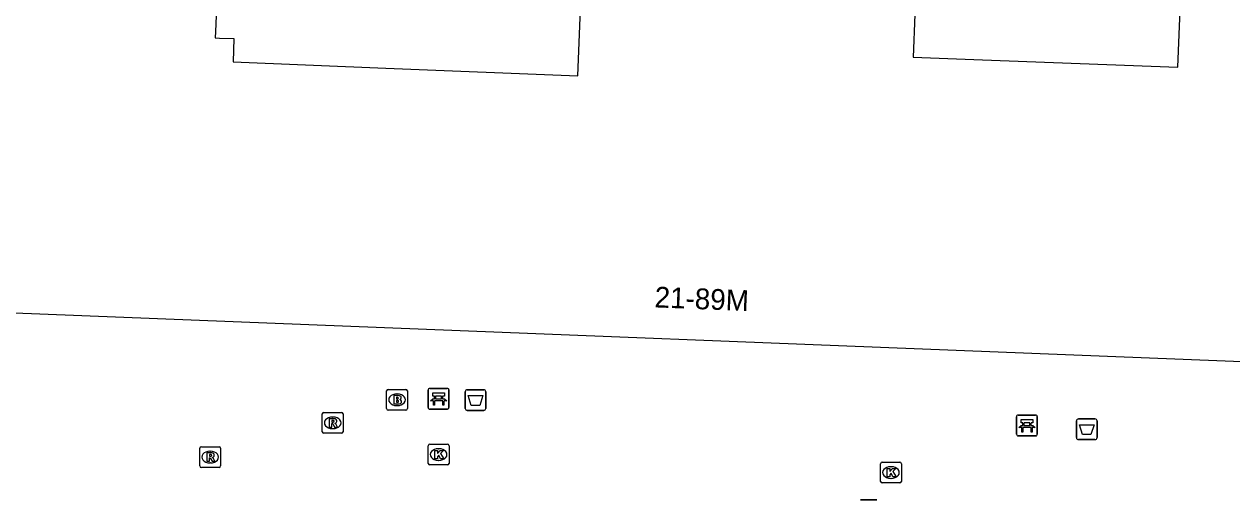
# Model space of a CAD drawing. Extents: x 160891 to 161384, y 386490 to 386907.
# Drawn here: x 161211.9 to 161270, y 386833.9 to 386856.8 of the extents above; entities that cross this region are included whole.
import ezdxf

# ---------------------------------------------------------------- set-up
doc = ezdxf.new("R2010")
doc.units = 0
for name, color, linetype in [('IMGEO_Afvalbak', 7, 'Continuous'), ('IMGEO_Bank', 7, 'Continuous'), ('IMGEO_Brandkraan', 7, 'Continuous'), ('IMGEO_Kolk', 7, 'Continuous'), ('IMGEO_Pand', 7, 'Continuous'), ('IMGEO_Pand_nummerreeks', 7, 'Continuous'), ('IMGEO_Reclamebord', 7, 'Continuous'), ('IMGEO_Rioolput', 7, 'Continuous')]:
    doc.layers.add(name, color=color, linetype=linetype)

msp = doc.modelspace()

# ---------------------------------------------------------------- linework, layer by layer
at = {"layer": 'IMGEO_Afvalbak'}
for p, q in [((161233.09, 386838.273), (161233.09, 386839.073)), ((161233.09, 386839.073), (161233.09, 386838.273)), ((161233.19, 386839.173), (161233.98, 386839.173)), ((161233.98, 386839.173), (161233.19, 386839.173)), ((161234.08, 386839.073), (161234.08, 386838.273)), ((161234.08, 386838.273), (161234.08, 386839.073)), ((161233.98, 386838.173), (161233.19, 386838.173)), ((161233.19, 386838.173), (161233.98, 386838.173)), ((161262.495, 386836.869), (161262.495, 386837.669)), ((161262.495, 386837.669), (161262.495, 386836.869)), ((161262.595, 386837.769), (161263.385, 386837.769)), ((161263.385, 386837.769), (161262.595, 386837.769)), ((161263.485, 386837.669), (161263.485, 386836.869)), ((161263.485, 386836.869), (161263.485, 386837.669)), ((161263.385, 386836.769), (161262.595, 386836.769)), ((161262.595, 386836.769), (161263.385, 386836.769))]:
    msp.add_line(p, q, dxfattribs=at)
for points in [[(161233.233, 386838.887), (161233.937, 386838.887), (161233.788, 386838.417), (161233.382, 386838.417), (161233.233, 386838.887)], [(161262.638, 386837.483), (161263.342, 386837.483), (161263.193, 386837.013), (161262.787, 386837.013), (161262.638, 386837.483)]]:
    msp.add_lwpolyline(points, dxfattribs=at)
for centre, start, end in [((161233.19, 386839.073), 90, 180), ((161233.19, 386839.073), 90, 180), ((161233.98, 386839.073), 0, 90), ((161233.98, 386839.073), 360, 90), ((161233.19, 386838.273), 180, 270), ((161233.19, 386838.273), 180, 270), ((161233.98, 386838.273), 270, 0), ((161233.98, 386838.273), 270, 0), ((161262.595, 386837.669), 90, 180), ((161262.595, 386837.669), 90, 180), ((161263.385, 386837.669), 0, 90), ((161263.385, 386837.669), 360, 90), ((161262.595, 386836.869), 180, 270), ((161262.595, 386836.869), 180, 270), ((161263.385, 386836.869), 270, 0), ((161263.385, 386836.869), 270, 0)]:
    msp.add_arc(centre, 0.1, start, end, dxfattribs=at)
at = {"layer": 'IMGEO_Bank'}
for p, q in [((161231.308, 386838.312), (161231.308, 386839.153)), ((161231.308, 386839.153), (161231.308, 386838.312)), ((161231.383, 386839.237), (161232.224, 386839.237)), ((161232.224, 386839.237), (161231.383, 386839.237)), ((161231.617, 386838.743), (161231.617, 386838.849)), ((161231.661, 386838.849), (161231.661, 386838.743)), ((161231.949, 386838.855), (161231.667, 386838.855)), ((161231.955, 386838.743), (161231.955, 386838.849)), ((161231.999, 386838.849), (161231.999, 386838.743)), ((161232.308, 386839.162), (161232.308, 386838.321)), ((161232.308, 386838.321), (161232.308, 386839.162)), ((161232.233, 386838.237), (161231.392, 386838.237)), ((161231.392, 386838.237), (161232.233, 386838.237)), ((161232.005, 386838.635), (161231.612, 386838.635)), ((161231.667, 386838.737), (161231.949, 386838.737)), ((161259.612, 386837.027), (161259.612, 386837.868)), ((161259.612, 386837.868), (161259.612, 386837.027)), ((161259.687, 386837.952), (161260.528, 386837.952)), ((161260.528, 386837.952), (161259.687, 386837.952)), ((161260.612, 386837.877), (161260.612, 386837.036)), ((161260.612, 386837.036), (161260.612, 386837.877)), ((161260.309, 386837.35), (161259.916, 386837.35)), ((161259.921, 386837.458), (161259.921, 386837.564)), ((161259.965, 386837.564), (161259.965, 386837.458)), ((161260.253, 386837.57), (161259.971, 386837.57)), ((161259.971, 386837.452), (161260.253, 386837.452)), ((161260.259, 386837.458), (161260.259, 386837.564)), ((161260.303, 386837.564), (161260.303, 386837.458)), ((161260.537, 386836.952), (161259.696, 386836.952)), ((161259.696, 386836.952), (161260.537, 386836.952))]:
    msp.add_line(p, q, dxfattribs=at)
for points in [[(161231.611, 386838.855), (161231.525, 386838.855), (161231.525, 386839.016), (161232.088, 386839.016), (161232.088, 386838.855), (161232.005, 386838.855)], [(161231.555, 386838.635), (161231.413, 386838.635), (161231.525, 386838.737), (161231.611, 386838.737)], [(161231.605, 386838.628), (161231.605, 386838.421), (161231.562, 386838.421), (161231.562, 386838.628)], [(161232.005, 386838.737), (161232.088, 386838.737), (161232.2, 386838.635), (161232.061, 386838.635)], [(161232.055, 386838.628), (161232.055, 386838.421), (161232.011, 386838.421), (161232.011, 386838.628)], [(161259.915, 386837.57), (161259.829, 386837.57), (161259.829, 386837.731), (161260.392, 386837.731), (161260.392, 386837.57), (161260.309, 386837.57)], [(161259.859, 386837.35), (161259.717, 386837.35), (161259.829, 386837.452), (161259.915, 386837.452)], [(161259.909, 386837.343), (161259.909, 386837.136), (161259.866, 386837.136), (161259.866, 386837.343)], [(161260.309, 386837.452), (161260.392, 386837.452), (161260.504, 386837.35), (161260.365, 386837.35)], [(161260.359, 386837.343), (161260.359, 386837.136), (161260.315, 386837.136), (161260.315, 386837.343)]]:
    msp.add_lwpolyline(points, dxfattribs=at)
for centre, radius, start, end in [((161231.386, 386839.159), 0.0779, 92.4484, 184.28452), ((161231.386, 386839.159), 0.0779, 92.4484, 184.28452), ((161231.61, 386838.848), 0.00671, 2.89567, 87.10433), ((161231.667, 386838.848), 0.00671, 92.89567, 177.10433), ((161231.949, 386838.848), 0.00671, 2.89567, 87.10433), ((161232.006, 386838.848), 0.00671, 92.89567, 177.10433), ((161232.23, 386839.159), 0.0779, 2.4484, 94.28452), ((161232.23, 386839.159), 0.0779, 2.4484, 94.28452), ((161231.386, 386838.315), 0.0779, 182.4484, 274.28452), ((161231.386, 386838.315), 0.0779, 182.4484, 274.28452), ((161231.555, 386838.628), 0.00671, 2.89567, 87.10433), ((161231.612, 386838.628), 0.00671, 92.89567, 177.10433), ((161231.61, 386838.744), 0.00671, 272.89567, 357.10433), ((161231.667, 386838.744), 0.00671, 182.89567, 267.10433), ((161231.949, 386838.744), 0.00671, 272.89567, 357.10433), ((161232.006, 386838.744), 0.00671, 182.89567, 267.10433), ((161232.004, 386838.628), 0.00671, 2.89567, 87.10433), ((161232.061, 386838.628), 0.00671, 92.89567, 177.10433), ((161232.23, 386838.315), 0.0779, 272.4484, 4.28452), ((161232.23, 386838.315), 0.0779, 272.4484, 4.28452), ((161259.69, 386837.874), 0.0779, 92.4484, 184.28452), ((161259.69, 386837.874), 0.0779, 92.4484, 184.28452), ((161260.534, 386837.874), 0.0779, 2.4484, 94.28452), ((161260.534, 386837.874), 0.0779, 2.4484, 94.28452), ((161259.859, 386837.343), 0.00671, 2.89567, 87.10433), ((161259.916, 386837.343), 0.00671, 92.89567, 177.10433), ((161259.914, 386837.563), 0.00671, 2.89567, 87.10433), ((161259.914, 386837.459), 0.00671, 272.89567, 357.10433), ((161259.971, 386837.563), 0.00671, 92.89567, 177.10433), ((161259.971, 386837.459), 0.00671, 182.89567, 267.10433), ((161260.253, 386837.563), 0.00671, 2.89567, 87.10433), ((161260.253, 386837.459), 0.00671, 272.89567, 357.10433), ((161260.31, 386837.563), 0.00671, 92.89567, 177.10433), ((161260.31, 386837.459), 0.00671, 182.89567, 267.10433), ((161260.308, 386837.343), 0.00671, 2.89567, 87.10433), ((161260.365, 386837.343), 0.00671, 92.89567, 177.10433), ((161259.69, 386837.03), 0.0779, 182.4484, 274.28452), ((161259.69, 386837.03), 0.0779, 182.4484, 274.28452), ((161260.534, 386837.03), 0.0779, 272.4484, 4.28452), ((161260.534, 386837.03), 0.0779, 272.4484, 4.28452)]:
    msp.add_arc(centre, radius, start, end, dxfattribs=at)
at = {"layer": 'IMGEO_Brandkraan'}
for p, q in [((161229.31, 386838.262), (161229.31, 386839.114)), ((161229.385, 386839.188), (161230.237, 386839.188)), ((161229.798, 386838.968), (161229.823, 386838.968)), ((161230.311, 386839.114), (161230.311, 386838.262)), ((161229.821, 386838.408), (161229.796, 386838.408)), ((161230.237, 386838.188), (161229.385, 386838.188))]:
    msp.add_line(p, q, dxfattribs=at)
for points in [[(161229.31, 386838.262), (161229.31, 386839.114)], [(161229.385, 386839.188), (161230.237, 386839.188)], [(161229.658, 386838.888), (161229.658, 386838.488), (161229.871, 386838.488)], [(161229.889, 386838.888), (161229.658, 386838.888)], [(161229.837, 386838.807), (161229.783, 386838.807), (161229.783, 386838.731)], [(161230.311, 386839.114), (161230.311, 386838.262)], [(161229.783, 386838.731), (161229.836, 386838.731)], [(161229.845, 386838.655), (161229.783, 386838.655), (161229.783, 386838.574)], [(161229.783, 386838.574), (161229.845, 386838.574)], [(161230.237, 386838.188), (161229.385, 386838.188)]]:
    msp.add_lwpolyline(points, dxfattribs=at)
for centre, radius, start, end in [((161229.387, 386839.112), 0.0765, 91.55205, 178.44795), ((161229.387, 386839.112), 0.0765, 91.55205, 178.44795), ((161229.838, 386838.769), 0.0379, 267.82845, 90.93552), ((161229.893, 386838.743), 0.145, 59.4692, 91.53667), ((161229.918, 386838.79), 0.0922, 285.51372, 58.15012), ((161230.235, 386839.112), 0.0765, 1.55205, 88.44795), ((161230.235, 386839.112), 0.0765, 1.55205, 88.44795), ((161229.387, 386838.264), 0.0765, 181.55205, 268.44795), ((161229.387, 386838.264), 0.0765, 181.55205, 268.44795), ((161229.846, 386838.614), 0.0404, 269.87594, 90.50774), ((161229.877, 386838.739), 0.251, 268.66757, 293.53466), ((161229.923, 386838.598), 0.105, 301.31148, 78.98903), ((161230.235, 386838.264), 0.0765, 271.55205, 358.44795), ((161230.235, 386838.264), 0.0765, 271.55205, 358.44795)]:
    msp.add_arc(centre, radius, start, end, dxfattribs=at)
for centre, major_axis, ratio, start_param, end_param in [((161229.797, 386838.688), (-0.387, 0.002), 0.722429, 4.712389, 7.853982), ((161229.822, 386838.688), (-0.39, 0.002), 0.717154, 1.570796, 4.712389)]:
    msp.add_ellipse(centre, major_axis=major_axis, ratio=ratio, start_param=start_param, end_param=end_param, dxfattribs=at)
at = {"layer": 'IMGEO_Kolk'}
for p, q in [((161231.311, 386835.627), (161231.311, 386836.479)), ((161231.386, 386836.553), (161232.238, 386836.553)), ((161232.312, 386836.479), (161232.312, 386835.627)), ((161231.799, 386836.333), (161231.824, 386836.333)), ((161232.238, 386835.553), (161231.386, 386835.553)), ((161231.822, 386835.773), (161231.797, 386835.773)), ((161253.072, 386834.761), (161253.072, 386835.613)), ((161253.147, 386835.687), (161253.999, 386835.687)), ((161253.56, 386835.467), (161253.585, 386835.467)), ((161254.073, 386835.613), (161254.073, 386834.761)), ((161253.583, 386834.907), (161253.558, 386834.907)), ((161253.999, 386834.687), (161253.147, 386834.687))]:
    msp.add_line(p, q, dxfattribs=at)
for points in [[(161231.311, 386835.627), (161231.311, 386836.479)], [(161231.386, 386836.553), (161232.238, 386836.553)], [(161232.312, 386836.479), (161232.312, 386835.627)], [(161231.632, 386836.253), (161231.755, 386836.253), (161231.755, 386836.102), (161231.885, 386836.253), (161232.049, 386836.253), (161231.903, 386836.102), (161232.056, 386835.853), (161231.904, 386835.853), (161231.819, 386836.017), (161231.755, 386835.95), (161231.755, 386835.853), (161231.632, 386835.853), (161231.632, 386836.253)], [(161232.238, 386835.553), (161231.386, 386835.553)], [(161253.072, 386834.761), (161253.072, 386835.613)], [(161253.147, 386835.687), (161253.999, 386835.687)], [(161253.393, 386835.387), (161253.516, 386835.387), (161253.516, 386835.236), (161253.646, 386835.387), (161253.81, 386835.387), (161253.664, 386835.236), (161253.817, 386834.987), (161253.665, 386834.987), (161253.58, 386835.151), (161253.516, 386835.084), (161253.516, 386834.987), (161253.393, 386834.987), (161253.393, 386835.387)], [(161254.073, 386835.613), (161254.073, 386834.761)], [(161253.999, 386834.687), (161253.147, 386834.687)]]:
    msp.add_lwpolyline(points, dxfattribs=at)
for centre, start, end in [((161231.388, 386836.477), 91.55205, 178.44795), ((161231.388, 386836.477), 91.55205, 178.44795), ((161232.236, 386836.477), 1.55205, 88.44795), ((161232.236, 386836.477), 1.55205, 88.44795), ((161231.388, 386835.629), 181.55205, 268.44795), ((161231.388, 386835.629), 181.55205, 268.44795), ((161232.236, 386835.629), 271.55205, 358.44795), ((161232.236, 386835.629), 271.55205, 358.44795), ((161253.149, 386835.611), 91.55205, 178.44795), ((161253.149, 386835.611), 91.55205, 178.44795), ((161253.997, 386835.611), 1.55205, 88.44795), ((161253.997, 386835.611), 1.55205, 88.44795), ((161253.149, 386834.763), 181.55205, 268.44795), ((161253.149, 386834.763), 181.55205, 268.44795), ((161253.997, 386834.763), 271.55205, 358.44795), ((161253.997, 386834.763), 271.55205, 358.44795)]:
    msp.add_arc(centre, 0.0765, start, end, dxfattribs=at)
for centre, major_axis, ratio, start_param, end_param in [((161231.798, 386836.053), (-0.387, 0.002), 0.722429, 4.712389, 7.853982), ((161231.823, 386836.053), (-0.39, 0.002), 0.717154, 1.570796, 4.712389), ((161253.559, 386835.187), (-0.387, 0.002), 0.722429, 4.712389, 7.853982), ((161253.584, 386835.187), (-0.39, 0.002), 0.717154, 1.570796, 4.712389)]:
    msp.add_ellipse(centre, major_axis=major_axis, ratio=ratio, start_param=start_param, end_param=end_param, dxfattribs=at)
at = {"layer": 'IMGEO_Pand'}
for points in [[(161222.369, 386886.248), (161221.375, 386860.939), (161221.275, 386860.943), (161221.078, 386856.403), (161221.066, 386856.099), (161221.271, 386856.091), (161221.965, 386856.062), (161221.919, 386854.943), (161229.279, 386854.644), (161238.505, 386854.269), (161238.86, 386863.105), (161248.886, 386860.967), (161254.82, 386859.706), (161254.804, 386859.3), (161254.641, 386855.168), (161257.979, 386855.044), (161267.366, 386854.695), (161267.493, 386857.839), (161277.574, 386857.417), (161277.385, 386852.718), (161283.395, 386852.488)], [(161282.19, 386840.045), (161203.707, 386843.159)]]:
    msp.add_lwpolyline(points, dxfattribs=at)
at = {"layer": 'IMGEO_Reclamebord'}
for p, q in [((161252.108, 386833.873), (161252.898, 386833.873)), ((161252.898, 386833.873), (161252.108, 386833.873))]:
    msp.add_line(p, q, dxfattribs=at)
at = {"layer": 'IMGEO_Rioolput'}
for p, q in [((161226.214, 386837.151), (161226.214, 386838.003)), ((161226.289, 386838.077), (161227.141, 386838.077)), ((161226.702, 386837.857), (161226.727, 386837.857)), ((161227.215, 386838.003), (161227.215, 386837.151)), ((161227.141, 386837.077), (161226.289, 386837.077)), ((161226.725, 386837.297), (161226.7, 386837.297)), ((161220.321, 386835.504), (161220.321, 386836.356)), ((161220.396, 386836.43), (161221.248, 386836.43)), ((161220.809, 386836.21), (161220.834, 386836.21)), ((161221.322, 386836.356), (161221.322, 386835.504)), ((161221.248, 386835.43), (161220.396, 386835.43)), ((161220.832, 386835.65), (161220.807, 386835.65))]:
    msp.add_line(p, q, dxfattribs=at)
for points in [[(161226.214, 386837.151), (161226.214, 386838.003)], [(161226.289, 386838.077), (161227.141, 386838.077)], [(161226.803, 386837.775), (161226.551, 386837.777), (161226.551, 386837.377)], [(161226.729, 386837.696), (161226.675, 386837.696), (161226.675, 386837.615)], [(161227.215, 386838.003), (161227.215, 386837.151)], [(161227.141, 386837.077), (161226.289, 386837.077)], [(161226.551, 386837.377), (161226.675, 386837.377), (161226.675, 386837.539), (161226.686, 386837.539)], [(161226.675, 386837.615), (161226.727, 386837.615)], [(161226.733, 386837.51), (161226.804, 386837.377), (161226.944, 386837.377), (161226.879, 386837.503)], [(161220.321, 386835.504), (161220.321, 386836.356)], [(161220.396, 386836.43), (161221.248, 386836.43)], [(161220.91, 386836.128), (161220.658, 386836.13), (161220.658, 386835.73)], [(161220.658, 386835.73), (161220.782, 386835.73), (161220.782, 386835.892), (161220.793, 386835.892)], [(161220.836, 386836.049), (161220.782, 386836.049), (161220.782, 386835.968)], [(161220.782, 386835.968), (161220.834, 386835.968)], [(161221.322, 386836.356), (161221.322, 386835.504)], [(161221.248, 386835.43), (161220.396, 386835.43)], [(161220.84, 386835.863), (161220.911, 386835.73), (161221.051, 386835.73), (161220.986, 386835.856)]]:
    msp.add_lwpolyline(points, dxfattribs=at)
for centre, radius, start, end in [((161226.291, 386838.001), 0.0765, 91.55205, 178.44795), ((161226.291, 386838.001), 0.0765, 91.55205, 178.44795), ((161226.735, 386837.6), 0.0964, 77.00612, 93.18647), ((161226.749, 386837.657), 0.0378, 276.66336, 79.67722), ((161226.802, 386837.665), 0.109, 350.36119, 89.41601), ((161226.8, 386837.665), 0.112, 277.58423, 350.98172), ((161227.139, 386838.001), 0.0765, 1.55205, 88.44795), ((161227.139, 386838.001), 0.0765, 1.55205, 88.44795), ((161226.291, 386837.153), 0.0765, 181.55205, 268.44795), ((161226.291, 386837.153), 0.0765, 181.55205, 268.44795), ((161226.685, 386837.486), 0.0533, 26.02933, 88.69889), ((161226.711, 386837.804), 0.19, 274.7715, 282.96867), ((161226.784, 386837.45), 0.108, 29.51342, 73.79051), ((161227.139, 386837.153), 0.0765, 271.55205, 358.44795), ((161227.139, 386837.153), 0.0765, 271.55205, 358.44795), ((161220.398, 386836.354), 0.0765, 91.55205, 178.44795), ((161220.398, 386836.354), 0.0765, 91.55205, 178.44795), ((161220.792, 386835.839), 0.0533, 26.02933, 88.69889), ((161220.818, 386836.157), 0.19, 274.7715, 282.96867), ((161220.842, 386835.953), 0.0964, 77.00612, 93.18647), ((161220.856, 386836.01), 0.0378, 276.66336, 79.67722), ((161220.909, 386836.018), 0.109, 350.36119, 89.41601), ((161220.907, 386836.018), 0.112, 277.58423, 350.98172), ((161220.891, 386835.803), 0.108, 29.51342, 73.79051), ((161221.246, 386836.354), 0.0765, 1.55205, 88.44795), ((161221.246, 386836.354), 0.0765, 1.55205, 88.44795), ((161220.398, 386835.506), 0.0765, 181.55205, 268.44795), ((161220.398, 386835.506), 0.0765, 181.55205, 268.44795), ((161221.246, 386835.506), 0.0765, 271.55205, 358.44795), ((161221.246, 386835.506), 0.0765, 271.55205, 358.44795)]:
    msp.add_arc(centre, radius, start, end, dxfattribs=at)
for centre, major_axis, ratio, start_param, end_param in [((161226.701, 386837.577), (-0.387, 0.002), 0.722429, 4.712389, 7.853982), ((161226.726, 386837.577), (-0.39, 0.002), 0.717154, 1.570796, 4.712389), ((161220.808, 386835.93), (-0.387, 0.002), 0.722429, 4.712389, 7.853982), ((161220.833, 386835.93), (-0.39, 0.002), 0.717154, 1.570796, 4.712389)]:
    msp.add_ellipse(centre, major_axis=major_axis, ratio=ratio, start_param=start_param, end_param=end_param, dxfattribs=at)

# ---------------------------------------------------------------- texts
at = {"layer": 'IMGEO_Pand_nummerreeks'}
msp.add_text('21-89M', height=1, rotation=357.72536, dxfattribs=at).set_placement((161242.186, 386843.134))

doc.saveas('drawing.dxf')
